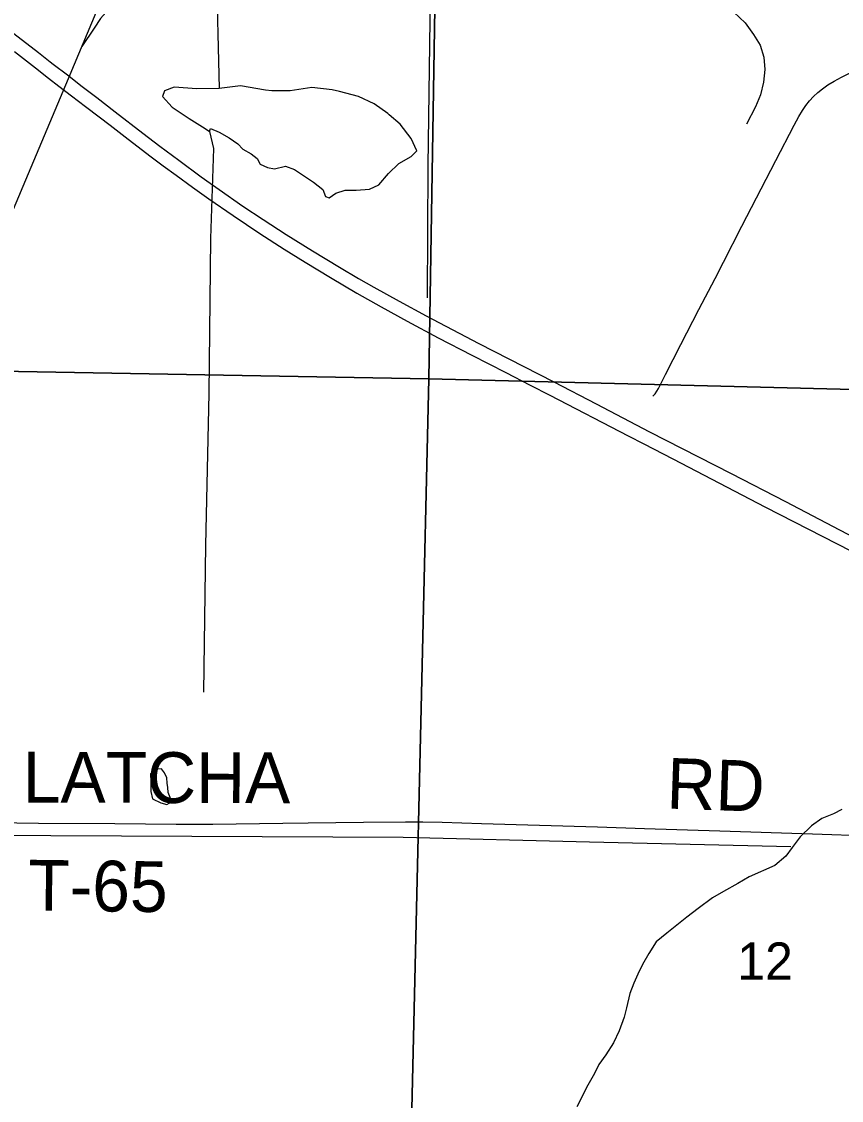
# Model space of a CAD drawing. Extents: x 0 to 34, y 0 to 22.
# Drawn here: x 7.043 to 7.962, y 16.1 to 17.308 of the extents above; entities that cross this region are included whole.
import ezdxf

# ---------------------------------------------------------------- set-up
doc = ezdxf.new("R2010")
doc.units = 0
for name, color, linetype in [('GM_X_Corporation', 7, 'Continuous'), ('GM_X_Interstate_Route', 7, 'Continuous'), ('GM_X_Minor_Lake', 7, 'Continuous'), ('GM_X_Minor_River', 7, 'Continuous'), ('GM_X_Rail_Line', 7, 'Continuous'), ('GM_X_Section_Text', 7, 'Continuous'), ('GM_X_Township_Road', 7, 'Continuous'), ('GM_X_Township_Road_Text', 7, 'Continuous')]:
    doc.layers.add(name, color=color, linetype=linetype)

msp = doc.modelspace()

# ---------------------------------------------------------------- linework, layer by layer
at = {"layer": 'GM_X_Corporation'}
for points in [[(6.497, 17.8754), (7.515, 17.8763), (7.4991, 16.9078), (6.4745, 16.9262)], [(7.515, 17.8763), (8.5579, 17.8652), (8.5553, 17.7758), (8.5049, 17.4227), (8.4956, 16.8828), (7.4991, 16.9078)], [(6.4745, 16.9262), (7.4991, 16.9078), (7.4758, 15.8976), (6.4581, 15.916)], [(7.4991, 16.9078), (8.4956, 16.8828), (8.4859, 16.4125), (8.4788, 15.8782), (7.4758, 15.8976)]]:
    msp.add_lwpolyline(points, close=True, dxfattribs=at)
at = {"layer": 'GM_X_Interstate_Route'}
for points in [[(7.0291, 17.2985), (7.0616, 17.2735), (7.0749, 17.2632), (7.0783, 17.2605), (7.0941, 17.2484), (7.1108, 17.2355), (7.1271, 17.223), (7.1478, 17.2071), (7.1788, 17.1831), (7.1976, 17.1687), (7.219, 17.1527), (7.244, 17.1343), (7.2643, 17.1199), (7.2909, 17.1015), (7.3137, 17.0863), (7.3393, 17.0698), (7.3688, 17.0513), (7.3991, 17.033), (7.4206, 17.0203), (7.4378, 17.0105), (7.4661, 16.9948), (7.4963, 16.9786), (7.5552, 16.9477), (7.6394, 16.9047), (7.6868, 16.88), (7.7468, 16.8486), (7.8382, 16.8019), (7.8989, 16.7704), (7.9596, 16.7389), (8.0078, 16.7138)], [(7.0347, 17.2746), (7.045, 17.2666), (7.0582, 17.2563), (7.073, 17.2448), (7.0847, 17.2357), (7.0986, 17.2251), (7.1144, 17.2131), (7.1297, 17.2014), (7.1421, 17.1919), (7.1588, 17.179), (7.1865, 17.1579), (7.2014, 17.1467), (7.2159, 17.1359), (7.2345, 17.1225), (7.2528, 17.1095), (7.2799, 17.0909), (7.3098, 17.0708), (7.337, 17.0532), (7.3607, 17.0385), (7.3889, 17.0214), (7.4184, 17.0041), (7.4459, 16.9885), (7.4748, 16.9726), (7.5099, 16.9539), (7.5474, 16.9344), (7.5856, 16.9149), (7.6127, 16.901), (7.6349, 16.8896), (7.7226, 16.8442), (7.7403, 16.835), (7.7729, 16.8182), (7.8766, 16.7643), (7.9724, 16.7153)]]:
    msp.add_lwpolyline(points, dxfattribs=at)
at = {"layer": 'GM_X_Minor_Lake'}
for p, q in [((7.4203, 17.2242), (7.3993, 17.2297)), ((7.2067, 16.4502), (7.206, 16.4552))]:
    msp.add_line(p, q, dxfattribs=at)
for points in [[(7.3993, 17.2297), (7.391, 17.2317), (7.3683, 17.2343), (7.3437, 17.2304), (7.3233, 17.2307), (7.3162, 17.2312), (7.2883, 17.2361), (7.2644, 17.233), (7.2391, 17.2329), (7.2138, 17.2347), (7.2028, 17.2307), (7.2009, 17.2243), (7.2117, 17.2124), (7.2308, 17.1996), (7.2484, 17.1884), (7.2536, 17.1849), (7.2544, 17.1883), (7.2642, 17.1844), (7.2754, 17.1778), (7.2852, 17.1712), (7.2908, 17.1651), (7.3001, 17.16), (7.3069, 17.1546), (7.3102, 17.1485), (7.3185, 17.1446), (7.3264, 17.143), (7.3385, 17.1462), (7.3486, 17.1423), (7.3599, 17.135), (7.37, 17.1284), (7.3805, 17.1199), (7.3834, 17.1123), (7.3875, 17.1107), (7.3952, 17.1159), (7.4054, 17.1192), (7.4179, 17.1194), (7.4326, 17.1204), (7.4432, 17.1252), (7.454, 17.1379), (7.4658, 17.1492), (7.4795, 17.157), (7.4857, 17.1634), (7.4794, 17.1771), (7.4672, 17.1932), (7.4548, 17.2036), (7.4533, 17.2051), (7.438, 17.216), (7.4203, 17.2242)], [(7.206, 16.4552), (7.2057, 16.4609), (7.2031, 16.4666), (7.1998, 16.4712), (7.193, 16.4709), (7.1873, 16.4657), (7.1875, 16.4566), (7.1878, 16.4459), (7.1896, 16.4375), (7.1989, 16.4329), (7.2057, 16.4313), (7.2107, 16.4342), (7.2092, 16.4392), (7.207, 16.4445), (7.2067, 16.4502)]]:
    msp.add_lwpolyline(points, dxfattribs=at)
at = {"layer": 'GM_X_Minor_River'}
for points in [[(7.3401, 17.8018), (7.2957, 17.6934), (7.2633, 17.6167), (7.2611, 17.4976), (7.2609, 17.3708), (7.2644, 17.233)], [(7.5003, 17.7732), (7.5029, 17.5648), (7.5011, 17.3644), (7.4983, 17.1465), (7.4975, 16.9988)], [(7.2536, 17.1849), (7.2579, 17.1659), (7.2547, 17.0653), (7.2525, 16.8915), (7.2488, 16.7215), (7.2466, 16.5571)], [(7.9623, 16.4255), (7.9528, 16.4207), (7.9399, 16.4156), (7.9281, 16.4074), (7.9155, 16.395), (7.9066, 16.383), (7.8993, 16.3732), (7.8871, 16.3627), (7.8582, 16.3502), (7.8457, 16.3427), (7.8297, 16.3338), (7.8171, 16.3268), (7.8011, 16.3148), (7.7885, 16.3051), (7.7755, 16.2947)], [(7.9051, 16.3837), (7.6793, 16.3889), (7.4704, 16.3942), (6.9963, 16.3963)], [(7.7755, 16.2947), (7.766, 16.2872), (7.7541, 16.2775), (7.7457, 16.2643), (7.7387, 16.2519), (7.7336, 16.2413), (7.729, 16.2311), (7.7247, 16.2194), (7.7207, 16.2035), (7.7183, 16.1929), (7.7128, 16.1778), (7.7062, 16.1642), (7.6977, 16.1507), (7.69, 16.1401), (7.685, 16.1299), (7.6776, 16.1167), (7.6652, 16.0926)]]:
    msp.add_lwpolyline(points, dxfattribs=at)
at = {"layer": 'GM_X_Rail_Line'}
for points in [[(5.7724, 14.1), (5.9023, 14.4065), (6.108, 14.9012), (7.0925, 17.2371), (7.3462, 17.8422), (7.5826, 18.397), (7.8741, 19.1084), (7.9022, 19.1708), (7.9338, 19.2375), (7.9584, 19.2815), (7.9927, 19.3184), (8.0524, 19.3602), (8.3458, 19.5368)], [(7.3155, 17.7352), (7.3107, 17.7171), (7.2444, 17.5558), (7.1962, 17.4406), (7.1664, 17.3679), (7.1531, 17.3388), (7.1402, 17.3215), (7.1312, 17.3115), (7.1243, 17.3008), (7.1105, 17.2801)], [(7.6821, 17.4033), (7.7005, 17.3921), (7.8289, 17.3255), (7.8411, 17.3186), (7.8539, 17.3068), (7.8633, 17.2938), (7.8706, 17.2817), (7.8748, 17.2684), (7.8758, 17.2543), (7.8744, 17.2402), (7.8712, 17.2261), (7.8655, 17.2127), (7.8554, 17.1931)]]:
    msp.add_lwpolyline(points, dxfattribs=at)
at = {"layer": 'GM_X_Township_Road'}
for points in [[(7.7503, 16.8884), (7.7529, 16.8912), (7.7548, 16.894), (7.7567, 16.8973), (7.7644, 16.9127), (7.7819, 16.9464), (7.8021, 16.9856), (7.8201, 17.0204), (7.8294, 17.0387), (7.8501, 17.079), (7.8882, 17.1524), (7.9086, 17.1922), (7.9139, 17.2019), (7.918, 17.2087), (7.9218, 17.2142), (7.926, 17.2193), (7.9305, 17.2242), (7.9353, 17.2287), (7.9404, 17.2329), (7.9464, 17.2371), (7.9537, 17.2415), (7.9617, 17.2457), (7.9813, 17.2557)], [(6.9807, 16.4115), (6.9883, 16.4114), (7.0616, 16.4104), (7.1474, 16.4098), (7.2161, 16.4092), (7.2571, 16.4093), (7.3355, 16.4101), (7.3641, 16.4105), (7.4261, 16.4113), (7.4732, 16.4118), (7.4925, 16.4118), (7.5142, 16.4114), (7.5583, 16.4099), (7.6882, 16.4061), (7.741, 16.4042), (7.8256, 16.4018), (7.9293, 16.3982), (7.9939, 16.3959), (7.9972, 16.3958)]]:
    msp.add_lwpolyline(points, dxfattribs=at)

# ---------------------------------------------------------------- texts
at = {"layer": 'GM_X_Section_Text'}
msp.add_text('12', height=0.04186, rotation=0, dxfattribs=at).set_placement((7.845, 16.2348))
at = {"layer": 'GM_X_Township_Road_Text'}
for s, rotation, p in [('LATCHA', 359.8371, (7.0441, 16.4334)), ('RD', 358.0247, (7.7651, 16.4267)), ('T-65', 359.2896, (7.05, 16.3125))]:
    msp.add_text(s, height=0.05682, rotation=rotation, dxfattribs=at).set_placement(p)

doc.saveas('drawing.dxf')
